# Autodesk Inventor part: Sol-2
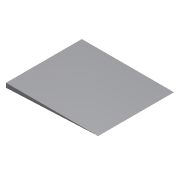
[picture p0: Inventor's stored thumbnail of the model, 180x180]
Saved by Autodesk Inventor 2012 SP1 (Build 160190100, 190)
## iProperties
Created: 2011-01
Part Number: Sol-2
Document SubType Name: Modeling
Designer: eric
Density: 1 g/cm^3
Material: Par défaut
Author: eric
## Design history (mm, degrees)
sketch "Esquisse1"
  geometry: L1 (-1144.405, -803.659)-(1012.544, -803.659); L2 (1012.544, -803.659)-(1012.544, 970.803); L3 (1012.544, 970.803)-(-1144.405, 970.803); L4 (-1144.405, 970.803)-(-1144.405, -803.659)
  constraints: 8 end point, 2 parallel, 1 horizontal, 1 perpendicular
extrude "Extrusion1" new body sketch "Esquisse1" distance "d0" = 100; taper "d1" = 0 deg
sketch "Esquisse2"
  geometry: L1 (0, 0)-(2156.949, 0) reference; L2 (2156.949, 0)-(2156.949, 100) reference; L3 (0, 0)-(2156.949, 100); L4 (0, 0)-(2156.949, 0); L5 (2156.949, 0)-(2156.949, 100); L6 (0, 0)-(0, 100) reference; L7 (0, 100)-(4.626, 0.214); L8 (0, 100)-(0, 0); 1 further point
  constraints: 10 end point, 3 collinear, 1 perpendicular, 1 point on line
extrude "Extrusion2" cut sketch "Esquisse2" stored distance "d2" = 10; taper "d3" = 0 deg
node "Solide1"
node "Corps solides"
node "Corps surfaciques"
